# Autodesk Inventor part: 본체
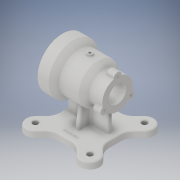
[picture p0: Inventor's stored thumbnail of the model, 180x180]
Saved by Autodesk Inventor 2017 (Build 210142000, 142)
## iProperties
Part Number: 본체
Material: 일반
Document SubType Name: Modeling
Designer: jhkim
Density: 1 g/cm^3
Appearance: 기본값
Author: jhkim
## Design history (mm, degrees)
sketch "스케치1"
  geometry: L1 (-45, -45)-(45, -45); L2 (45, -45)-(45, 45); L3 (45, 45)-(-45, 45); L4 (-45, 45)-(-45, -45); L5 (-45, -45)-(45, 45); L6 (45, -45)-(-45, 45); 1 further point
  constraints: 12 end point, 2 midpoint, 2 parallel, 1 horizontal, 1 perpendicular
  dimensions: "d0" = 90 distance of L3.end L2.end; "d1" = 90 distance of L2.end L1.end
extrude "돌출1" new body sketch "스케치1" distance "d2" = 12; taper "d3" = 0 deg
sketch "스케치2"
  geometry: L1 (49.497, 49.497)-(-49.497, -49.497); L2 (0, 0)-(78.808, 0); L3 (45, -45)-(-45, -45) reference; L4 (45, 45)-(45, -45) reference; L5 (-45, 45)-(45, 45) reference; L6 (-45, -45)-(-45, 45) reference; L7 (20.958, 45)-(37.477, 61.518); L8 (45, 20.958)-(61.518, 37.477); L9 (45, 45)-(45, -45) reference; L10 (45, 20.958)-(45, 45); L11 (45, 45)-(20.958, 45); L12 (-45, 45)-(45, 45) reference; L13 (45, 20.958)-(45, 45); L14 (-20.958, 45)-(-37.477, 61.518); L15 (-45, 20.958)-(-61.518, 37.477); L16 (-45, 45)-(-45, 20.958); L17 (-20.958, 45)-(-45, 45); L18 (-45, -20.958)-(-61.518, -37.477); L19 (-20.958, -45)-(-37.477, -61.518); L20 (-45, -45)-(-20.958, -45); L21 (-45, -20.958)-(-45, -45); L22 (20.958, -45)-(37.477, -61.518); L23 (45, -20.958)-(61.518, -37.477); L24 (45, -45)-(45, -20.958); L25 (20.958, -45)-(45, -45); A1 r 70 centre (0, 0) between (49.497, 49.497) and (-49.497, -49.497); A2 r 17 centre (49.497, 49.497) between (33.103, 45) and (45, 33.103); A3 r 17 centre (49.497, 49.497) between (61.518, 37.477) and (37.477, 61.518); A4 r 17 centre (-49.497, 49.497) between (-37.477, 61.518) and (-61.518, 37.477); A5 r 17 centre (-49.497, -49.497) between (-61.518, -37.477) and (-37.477, -61.518); A6 r 17 centre (49.497, -49.497) between (37.477, -61.518) and (61.518, -37.477); 1 further point
  constraints: 38 end point, 12 point on circle, 6 centre point, 3 point on line, 2 coincident, 2 collinear, 2 symmetric about line, 1 horizontal, 1 midpoint, 1 perpendicular, 1 tangent, 45 other
  dimensions: "d4" = 140 diameter of A1; "d5" = 45 deg angle of L2 L1; "d7" = 45 deg angle of L7 L2; "d10" = 360 deg dimension on point (0, 0) A2.centre (derived)
extrude "돌출2" join sketch "스케치2" distance "d12" = 12; taper "d13" = 0 deg
fillet "모깎기1" dims "d14" = 25
sketch "스케치3"
  geometry: L1 (37, -4)-(37, 4); L2 (-37, 4)-(-37, -4); L3 (-37, -4)-(37, 4); L4 (37, -4)-(-37, 4); L5 (-4, -25)-(4, -25); L6 (4, 25)-(-4, 25); L7 (-4, -25)-(4, 25); L8 (4, -25)-(-4, 25); L9 (37, 4)-(4, 4); L10 (-4, 4)-(-37, 4); L11 (-4, 25)-(-4, 4); L12 (4, -25)-(4, -4); L13 (4, 4)-(4, 25); L14 (-37, -4)-(-4, -4); L15 (4, -4)-(37, -4); L16 (-4, -4)-(-4, -25); 1 further point
  constraints: 32 end point, 10 parallel, 4 midpoint, 4 perpendicular, 3 horizontal
  dimensions: "d15" = 74 distance of L2.start L1.end; "d16" = 8 distance of L1.end L1.start; "d17" = 8 distance of L6.end L6.start; "d18" = 50 distance of L6.start L5.end; "d19" = 4 distance from line of L13 point (0, 0); "d20" = 4 distance from line of L10 point (0, 0); "d21" = 25 distance from line of L6 point (0, 0); "d22" = 37 distance from line of L2 point (0, 0)
node "작업 평면1"
sketch "스케치4"
  geometry: L1 (-50, 0)-(-50, 45); L2 (-50, 45)-(-30, 45); L3 (-30, 45)-(-19, 36); L4 (-19, 36)-(15, 36); L5 (15, 36)-(27, 27.5); L6 (27, 27.5)-(50, 27.5); L7 (50, 27.5)-(50, 0); L8 (-50, 0)-(50, 0); 1 further point
  constraints: 16 end point, 2 parallel, 2 perpendicular, 1 midpoint, 1 vertical
  dimensions: "d24" = 50 distance from line of L1 point (0, 0); "d25" = 90 diameter of L2 L8; "d26" = 20 distance from line of L2.end L1; "d27" = 65 distance from line of L4.end L1; "d28" = 23 distance from line of L7 L5.end; "d29" = 100 distance between parallel lines of L7 L1; "d30" = 55 diameter of L6 L8; "d31" = 72 diameter of L4 L8; "d32" = 31 distance from line of L3.end L1
revolve "회전1" sketch "스케치4" stored, may be unused: angle "d33" = 90 deg
sketch "스케치5"
  geometry: 1 further point
sketch "스케치6"
  geometry: C1 r 45 at (0, 0) reference; C2 r 35 at (0, 0); 1 further point
  constraints: 1 centre point, 1 coincident
  dimensions: "d34" = 70 diameter of C2
extrude "돌출3" cut sketch "스케치6" distance "d35" = 23; taper "d36" = 0 deg
sketch "스케치7"
  geometry: C1 r 35 at (0, 0) reference; C2 r 23.5 at (0, 0); 1 further point
  constraints: 1 centre point, 1 coincident
  dimensions: "d37" = 47 diameter of C2
extrude "돌출4" cut sketch "스케치7" distance "d38" = 47; taper "d39" = 0 deg
sketch "스케치8"
  geometry: C1 r 23.5 at (0, 0) reference; C2 r 15 at (0, 0); 1 further point
  constraints: 1 centre point, 1 coincident
  dimensions: "d40" = 30 diameter of C2
extrude "돌출5" cut sketch "스케치8" stored distance "d41" = 47; taper "d42" = 0 deg
fillet "모깎기2" dims "d43" = 3
chamfer "모따기1" distance "d44" = 1; stored, may be unused: second distance "d45" = 2, angle "d46" = 45 deg
extrude "돌출6" join sketch "스케치3" stored distance "d47" = 47; taper "d48" = 0 deg
feature "면 기울기1" dims angle "d49" = 10 deg
feature "면 기울기2" dims angle "d50" = 10 deg
sketch "스케치9"
  geometry: C1 r 7 at (-27.5, 0); C2 r 7 at (13.75, -23.816); C3 r 7 at (13.75, 23.816); 2 further points
  constraints: 3 centre point, 2 horizontal alignment, 8 other
  dimensions: "d51" = 7 radius of C1; "d54" = 360 deg dimension on point (0, 0) C1.centre (derived)
extrude "돌출7" join sketch "스케치9" distance "d56" = 15; taper "d57" = 0 deg
sketch "스케치10"
  geometry: C1 r 16 at (27.5, 0) reference; A1 r 27.5 centre (27.5, 0) between (34.792, 26.516) and (0.891, 6.943) reference; A2 r 7 centre (0, 0) between (0.891, 6.943) and (0.891, -6.943) reference; A3 r 27.5 centre (27.5, 0) between (0.891, -6.943) and (34.792, -26.516) reference; A4 r 7 centre (41.25, -23.816) between (34.792, -26.516) and (46.817, -19.573) reference; A5 r 27.5 centre (27.5, 0) between (46.817, -19.573) and (46.817, 19.573) reference; A6 r 7 centre (41.25, 23.816) between (46.817, 19.573) and (34.792, 26.516) reference; 4 further points
  constraints: 3 coincident
hole "구멍1" sketch "스케치10" at (0, 0), (41.25, -23.816), (41.25, 23.816) diameter "d58" = 3.242; stored, may be unused: countersink angle "d62" = 90 deg, drill point angle "d64" = 118 deg; dims "d59" = 9, "d60" = 4, "d61" = 2, "d63" = 11
sketch "스케치11" dims "d65" = 80
  geometry: C1 r 45 at (0, 0) reference; C2 r 36 at (0, 0) reference; 8 further points
  constraints: 2 horizontal alignment, 1 coincident, 9 other
  dimensions: "d68" = 360 deg dimension on C1.centre point (40, 0) (derived)
hole "구멍2" sketch "스케치11" at (40, 0), (20, 34.641), (-20, 34.641), (-40, 0), (-20, -34.641), (20, -34.641) diameter "d70" = 3.242; stored, may be unused: countersink angle "d74" = 90 deg, drill point angle "d76" = 118 deg; dims "d71" = 9, "d72" = 4, "d73" = 2, "d75" = 11
node "작업 평면2"
sketch "스케치12"
  geometry: L1 (50, 45)-(50, -45) reference; C1 r 5 at (0, 0); 1 further point
  constraints: 1 centre point, 1 coincident
  dimensions: "d78" = 10 diameter of C1
extrude "돌출8" join sketch "스케치12" stored distance "d79" = 15; taper "d80" = 0 deg
sketch "스케치13"
  geometry: 2 further points
  constraints: 1 coincident
hole "구멍3" sketch "스케치13" at (0, 0) diameter "d81" = 4.134; stored, may be unused: countersink angle "d85" = 90 deg, drill point angle "d87" = 118 deg; dims "d82" = 10, "d83" = 4, "d84" = 2, "d86" = 14.2
fillet "모깎기3" dims "d88" = 3
fillet "모깎기4" dims "d89" = 3
fillet "모깎기5" dims "d90" = 3
fillet "모깎기6" dims "d91" = 3
fillet "모깎기7" dims "d92" = 3
fillet "모깎기8" dims "d93" = 3
fillet "모깎기9" dims "d94" = 3
fillet "모깎기10" dims "d95" = 1
sketch "스케치14"
  geometry: L1 (-40, 1)-(-40, -1) reference; L2 (-7, 7)-(-34, 7) reference; L3 (-7, 21.425)-(-7, 7) reference; L4 (1, 27.517)-(-1, 27.517) reference; L5 (7, 7)-(7, 21.425) reference; L6 (34, 7)-(7, 7) reference; L7 (40, -1)-(40, 1) reference; L8 (7, -7)-(34, -7) reference; L9 (7, -21.425)-(7, -7) reference; L10 (-1, -27.517)-(1, -27.517) reference; L11 (-7, -7)-(-7, -21.425) reference; L12 (-34, -7)-(-7, -7) reference; L13 (39.598, -59.397)-(30.402, -50.201) reference; L14 (50.201, -30.402)-(59.397, -39.598) reference; L15 (42, 10.603)-(42, -10.603) reference; L16 (59.397, 39.598)-(50.201, 30.402) reference; L17 (30.402, 50.201)-(39.598, 59.397) reference; L18 (-10.603, 42)-(10.603, 42) reference; L19 (-39.598, 59.397)-(-30.402, 50.201) reference; L20 (-50.201, 30.402)-(-59.397, 39.598) reference; L21 (-42, -10.603)-(-42, 10.603) reference; L22 (-59.397, -39.598)-(-50.201, -30.402) reference; L23 (-30.402, -50.201)-(-39.598, -59.397) reference; L24 (10.603, -42)-(-10.603, -42) reference; A1 r 6 centre (-34, -1) between (-40, -1) and (-34, -7) reference; A2 r 6 centre (-34, 1) between (-34, 7) and (-40, 1) reference; A3 r 6 centre (34, 1) between (40, 1) and (34, 7) reference; A4 r 6 centre (34, -1) between (34, -7) and (40, -1) reference; A5 r 28 centre (10.603, -70) between (30.402, -50.201) and (10.603, -42) reference; A6 r 14 centre (49.497, -49.497) between (39.598, -59.397) and (59.397, -39.598) reference; A7 r 28 centre (70, -10.603) between (42, -10.603) and (50.201, -30.402) reference; A8 r 28 centre (70, 10.603) between (50.201, 30.402) and (42, 10.603) reference; A9 r 14 centre (49.497, 49.497) between (59.397, 39.598) and (39.598, 59.397) reference; A10 r 28 centre (10.603, 70) between (10.603, 42) and (30.402, 50.201) reference; A11 r 28 centre (-10.603, 70) between (-30.402, 50.201) and (-10.603, 42) reference; A12 r 14 centre (-49.497, 49.497) between (-39.598, 59.397) and (-59.397, 39.598) reference; A13 r 28 centre (-70, 10.603) between (-42, 10.603) and (-50.201, 30.402) reference; A14 r 28 centre (-70, -10.603) between (-50.201, -30.402) and (-42, -10.603) reference; A15 r 14 centre (-49.497, -49.497) between (-59.397, -39.598) and (-39.598, -59.397) reference; A16 r 28 centre (-10.603, -70) between (-10.603, -42) and (-30.402, -50.201) reference; 9 further points; 4 other entities
  constraints: 4 coincident, 4 other
hole "구멍4" sketch "스케치14" at (-49.497, 49.497), (-49.497, -49.497), (49.497, -49.497), (49.497, 49.497) diameter "d96" = 10; stored, may be unused: countersink angle "d100" = 90 deg, drill point angle "d102" = 0 deg; dims "d97" = 10, "d98" = 4, "d99" = 2, "d101" = 14.2
sketch "스케치15"
  geometry: 2 further points
  constraints: 1 vertical alignment, 1 other
  dimensions: "d103" = 35 distance of point (0, -35) point (0, 0)
feature "엠보싱1" sketch "스케치15" dims "d4" = 140, "d5" = 45 deg, "d7" = 45 deg, "d10" = 360 deg (derived), "d104" = 0.5, "d105" = 0
node "솔리드1"
node "투영된 루프1"
node "투영된 루프2"
node "투영된 루프3"
node "투영된 루프4"
node "투영된 루프5"
node "투영된 루프6"
node "투영된 루프7"
other parameters: "d6" = 34, "d23" = 82, "d77" = -122
